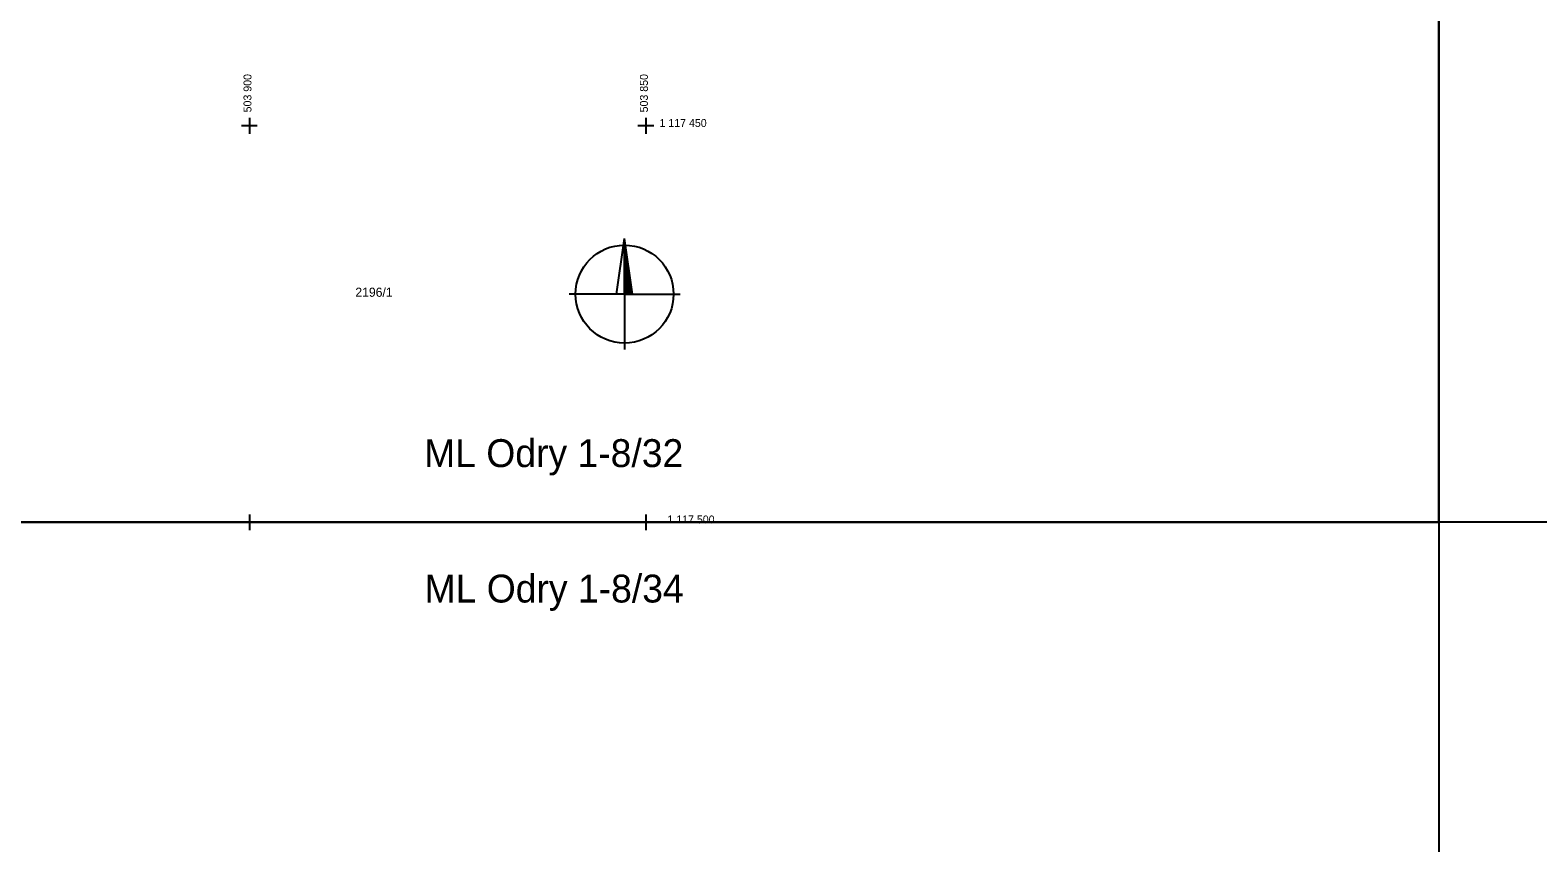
# Model space of a CAD drawing. Extents: x -504375 to -503125, y -1118000 to -1116474.
# Drawn here: x -503927.6 to -503737.5, y -1117540.4 to -1117437.9 of the extents above; entities that cross this region are included whole.
import ezdxf

# ---------------------------------------------------------------- set-up
doc = ezdxf.new("R2010")
doc.units = 0
for name, color, linetype in [('Podkladové mapy', 7, 'Continuous'), ('Síť dekadická', 7, 'Continuous'), ('Vrstva 34', 7, 'Continuous')]:
    doc.layers.add(name, color=color, linetype=linetype)

msp = doc.modelspace()

# ---------------------------------------------------------------- linework, layer by layer
at = {"layer": 'Síť dekadická'}
for points in [[(-503750, -1117000), (-503750, -1117500), (-504375, -1117500), (-504375, -1117000)], [(-503125, -1117000), (-503125, -1117500), (-503750, -1117500), (-503750, -1117000)], [(-503750, -1117500), (-503750, -1118000), (-504375, -1118000), (-504375, -1117500)]]:
    msp.add_lwpolyline(points, close=True, dxfattribs=at)
at = {"layer": 'Vrstva 34'}
for p, q in [((-503900, -1117449), (-503900, -1117451)), ((-503850, -1117449), (-503850, -1117451)), ((-503899, -1117450), (-503901, -1117450)), ((-503849, -1117450), (-503851, -1117450)), ((-503853.68, -1117471.23), (-503852.68, -1117464.23)), ((-503851.68, -1117471.23), (-503852.68, -1117464.23)), ((-503852.68, -1117471.23), (-503852.68, -1117464.23)), ((-503852.68, -1117464.274), (-503852.674, -1117464.274)), ((-503852.68, -1117464.324), (-503852.666, -1117464.324)), ((-503852.68, -1117464.374), (-503852.659, -1117464.374)), ((-503852.68, -1117464.424), (-503852.652, -1117464.424)), ((-503852.68, -1117464.474), (-503852.645, -1117464.474)), ((-503852.68, -1117464.524), (-503852.638, -1117464.524)), ((-503852.68, -1117464.574), (-503852.631, -1117464.574)), ((-503852.68, -1117464.624), (-503852.624, -1117464.624)), ((-503852.68, -1117464.674), (-503852.617, -1117464.674)), ((-503852.68, -1117464.724), (-503852.609, -1117464.724)), ((-503852.68, -1117464.774), (-503852.602, -1117464.774)), ((-503852.68, -1117464.824), (-503852.595, -1117464.824)), ((-503852.68, -1117464.874), (-503852.588, -1117464.874)), ((-503852.68, -1117464.924), (-503852.581, -1117464.924)), ((-503852.68, -1117464.974), (-503852.574, -1117464.974)), ((-503852.68, -1117465.024), (-503852.567, -1117465.024)), ((-503852.68, -1117465.084), (-503852.558, -1117465.084)), ((-503852.68, -1117465.134), (-503852.551, -1117465.134)), ((-503852.68, -1117465.184), (-503852.544, -1117465.184)), ((-503852.68, -1117465.234), (-503852.537, -1117465.234)), ((-503852.68, -1117465.284), (-503852.53, -1117465.284)), ((-503852.68, -1117465.334), (-503852.522, -1117465.334)), ((-503852.68, -1117465.384), (-503852.515, -1117465.384)), ((-503852.68, -1117465.434), (-503852.508, -1117465.434)), ((-503852.68, -1117465.484), (-503852.501, -1117465.484)), ((-503852.68, -1117465.534), (-503852.494, -1117465.534)), ((-503852.68, -1117465.584), (-503852.487, -1117465.584)), ((-503852.68, -1117465.634), (-503852.48, -1117465.634)), ((-503852.68, -1117465.684), (-503852.472, -1117465.684)), ((-503852.68, -1117465.734), (-503852.465, -1117465.734)), ((-503852.68, -1117465.784), (-503852.458, -1117465.784)), ((-503852.68, -1117465.834), (-503852.451, -1117465.834)), ((-503852.68, -1117465.884), (-503852.444, -1117465.884)), ((-503852.68, -1117465.934), (-503852.437, -1117465.934)), ((-503852.68, -1117465.984), (-503852.43, -1117465.984)), ((-503852.68, -1117466.034), (-503852.422, -1117466.034)), ((-503852.68, -1117466.084), (-503852.415, -1117466.084)), ((-503852.68, -1117466.134), (-503852.408, -1117466.134)), ((-503852.68, -1117466.184), (-503852.401, -1117466.184)), ((-503852.68, -1117466.234), (-503852.394, -1117466.234)), ((-503852.68, -1117466.284), (-503852.387, -1117466.284)), ((-503852.68, -1117466.334), (-503852.38, -1117466.334)), ((-503852.68, -1117466.384), (-503852.372, -1117466.384)), ((-503852.68, -1117466.434), (-503852.365, -1117466.434)), ((-503852.68, -1117466.484), (-503852.358, -1117466.484)), ((-503852.68, -1117466.534), (-503852.351, -1117466.534)), ((-503852.68, -1117466.584), (-503852.344, -1117466.584)), ((-503852.68, -1117466.634), (-503852.337, -1117466.634)), ((-503852.68, -1117466.684), (-503852.329, -1117466.684)), ((-503852.68, -1117466.734), (-503852.322, -1117466.734)), ((-503852.68, -1117466.784), (-503852.315, -1117466.784)), ((-503852.68, -1117466.834), (-503852.308, -1117466.834)), ((-503852.68, -1117466.884), (-503852.301, -1117466.884)), ((-503852.68, -1117466.934), (-503852.294, -1117466.934)), ((-503852.68, -1117466.984), (-503852.287, -1117466.984)), ((-503852.68, -1117467.034), (-503852.279, -1117467.034)), ((-503852.68, -1117467.084), (-503852.272, -1117467.084)), ((-503852.68, -1117467.134), (-503852.265, -1117467.134)), ((-503852.68, -1117467.184), (-503852.258, -1117467.184)), ((-503852.68, -1117467.234), (-503852.251, -1117467.234)), ((-503852.68, -1117467.284), (-503852.244, -1117467.284)), ((-503852.68, -1117467.334), (-503852.237, -1117467.334)), ((-503852.68, -1117467.384), (-503852.229, -1117467.384)), ((-503852.68, -1117467.434), (-503852.222, -1117467.434)), ((-503852.68, -1117467.484), (-503852.215, -1117467.484)), ((-503852.68, -1117467.534), (-503852.208, -1117467.534)), ((-503852.68, -1117467.584), (-503852.201, -1117467.584)), ((-503852.68, -1117467.634), (-503852.194, -1117467.634)), ((-503852.68, -1117467.684), (-503852.187, -1117467.684)), ((-503852.68, -1117467.734), (-503852.179, -1117467.734)), ((-503852.68, -1117467.784), (-503852.172, -1117467.784)), ((-503852.68, -1117467.834), (-503852.165, -1117467.834)), ((-503852.68, -1117467.884), (-503852.158, -1117467.884)), ((-503852.68, -1117467.934), (-503852.151, -1117467.934)), ((-503852.68, -1117467.984), (-503852.144, -1117467.984)), ((-503852.68, -1117468.034), (-503852.137, -1117468.034)), ((-503852.68, -1117468.084), (-503852.129, -1117468.084)), ((-503852.68, -1117468.134), (-503852.122, -1117468.134)), ((-503852.68, -1117468.184), (-503852.115, -1117468.184)), ((-503852.68, -1117468.234), (-503852.108, -1117468.234)), ((-503852.68, -1117468.284), (-503852.101, -1117468.284)), ((-503852.68, -1117468.334), (-503852.094, -1117468.334)), ((-503852.68, -1117468.384), (-503852.087, -1117468.384)), ((-503852.68, -1117468.434), (-503852.079, -1117468.434)), ((-503852.68, -1117468.484), (-503852.072, -1117468.484)), ((-503852.68, -1117468.534), (-503852.065, -1117468.534)), ((-503852.68, -1117468.584), (-503852.058, -1117468.584)), ((-503852.68, -1117468.634), (-503852.051, -1117468.634)), ((-503852.68, -1117468.684), (-503852.044, -1117468.684)), ((-503852.68, -1117468.734), (-503852.037, -1117468.734)), ((-503852.68, -1117468.784), (-503852.029, -1117468.784)), ((-503852.68, -1117468.834), (-503852.022, -1117468.834)), ((-503852.68, -1117468.884), (-503852.015, -1117468.884)), ((-503852.68, -1117468.934), (-503852.008, -1117468.934)), ((-503852.68, -1117468.984), (-503852.001, -1117468.984)), ((-503852.68, -1117469.034), (-503851.994, -1117469.034)), ((-503852.68, -1117469.084), (-503851.987, -1117469.084)), ((-503852.68, -1117469.134), (-503851.979, -1117469.134)), ((-503852.68, -1117469.184), (-503851.972, -1117469.184)), ((-503852.68, -1117469.234), (-503851.965, -1117469.234)), ((-503852.68, -1117469.284), (-503851.958, -1117469.284)), ((-503852.68, -1117469.334), (-503851.951, -1117469.334)), ((-503852.68, -1117469.384), (-503851.944, -1117469.384)), ((-503852.68, -1117469.434), (-503851.937, -1117469.434)), ((-503852.68, -1117469.484), (-503851.929, -1117469.484)), ((-503852.68, -1117469.534), (-503851.922, -1117469.534)), ((-503852.68, -1117469.584), (-503851.915, -1117469.584)), ((-503852.68, -1117469.634), (-503851.908, -1117469.634)), ((-503852.68, -1117469.684), (-503851.901, -1117469.684)), ((-503852.68, -1117469.734), (-503851.894, -1117469.734)), ((-503852.68, -1117469.784), (-503851.886, -1117469.784)), ((-503852.68, -1117469.834), (-503851.879, -1117469.834)), ((-503852.68, -1117469.884), (-503851.872, -1117469.884)), ((-503852.68, -1117469.934), (-503851.865, -1117469.934)), ((-503852.68, -1117469.984), (-503851.858, -1117469.984)), ((-503852.68, -1117470.034), (-503851.851, -1117470.034)), ((-503852.68, -1117470.084), (-503851.844, -1117470.084)), ((-503852.68, -1117470.134), (-503851.836, -1117470.134)), ((-503852.68, -1117470.184), (-503851.829, -1117470.184)), ((-503852.68, -1117470.234), (-503851.822, -1117470.234)), ((-503852.68, -1117470.284), (-503851.815, -1117470.284)), ((-503852.68, -1117470.334), (-503851.808, -1117470.334)), ((-503852.68, -1117470.384), (-503851.801, -1117470.384)), ((-503852.68, -1117470.434), (-503851.794, -1117470.434)), ((-503852.68, -1117470.484), (-503851.786, -1117470.484)), ((-503852.68, -1117470.534), (-503851.779, -1117470.534)), ((-503852.68, -1117470.584), (-503851.772, -1117470.584)), ((-503852.68, -1117470.634), (-503851.765, -1117470.634)), ((-503852.68, -1117470.684), (-503851.758, -1117470.684)), ((-503852.68, -1117471.23), (-503859.68, -1117471.23)), ((-503852.68, -1117470.734), (-503851.751, -1117470.734)), ((-503852.68, -1117470.784), (-503851.744, -1117470.784)), ((-503852.68, -1117470.834), (-503851.736, -1117470.834)), ((-503852.68, -1117470.884), (-503851.729, -1117470.884)), ((-503852.68, -1117470.934), (-503851.722, -1117470.934)), ((-503852.68, -1117470.984), (-503851.715, -1117470.984)), ((-503852.68, -1117471.034), (-503851.708, -1117471.034)), ((-503852.68, -1117471.084), (-503851.701, -1117471.084)), ((-503852.68, -1117471.134), (-503851.694, -1117471.134)), ((-503852.68, -1117471.184), (-503851.686, -1117471.184)), ((-503852.68, -1117471.23), (-503852.68, -1117478.23)), ((-503852.68, -1117471.23), (-503851.68, -1117471.23)), ((-503851.68, -1117471.23), (-503845.68, -1117471.23)), ((-503900, -1117499), (-503900, -1117501)), ((-503850, -1117499), (-503850, -1117501)), ((-503899, -1117500), (-503901, -1117500)), ((-503849, -1117500), (-503851, -1117500))]:
    msp.add_line(p, q, dxfattribs=at)
msp.add_lwpolyline([(-503831.557, -1117500), (-504108.579, -1117500)], dxfattribs=at)
msp.add_circle((-503852.68, -1117471.229), 6.18, dxfattribs=at)

# ---------------------------------------------------------------- texts
at = {"layer": 'Podkladové mapy'}
msp.add_text('2196/1', height=1.15, dxfattribs=at).set_placement((-503886.633, -1117471.566))
at = {"layer": 'Vrstva 34'}
for s, p in [('503 900', (-503899.738, -1117448.315)), ('503 850', (-503849.738, -1117448.315))]:
    msp.add_text(s, height=1, rotation=90, dxfattribs=at).set_placement(p)
for s, height, p in [('1 117 450', 1, (-503848.275, -1117450.153)), ('ML Odry 1-8/32', 3.518, (-503877.959, -1117493.039)), ('1 117 500', 1, (-503847.277, -1117500.143)), ('ML Odry 1-8/34', 3.518, (-503877.904, -1117510.115))]:
    msp.add_text(s, height=height, dxfattribs=at).set_placement(p)

doc.saveas('drawing.dxf')
